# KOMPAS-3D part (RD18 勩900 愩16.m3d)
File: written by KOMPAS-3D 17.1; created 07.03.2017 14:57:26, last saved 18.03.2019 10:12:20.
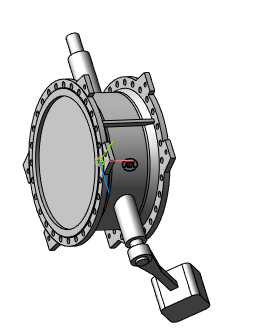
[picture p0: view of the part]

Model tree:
1. Операция без истории:2  (labels: Сталь 20  ГОСТ 1050-88)

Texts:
  RD18 Ду100 Ру16
  RD18 Ду150 Ру16
  RD18 Ду200 Ру16
  RD18 Ду250 Ру16
  RD18 Ду300 Ру16
  RD18 Ду350 Ру16
  RD18 Ду400 Ру10
  RD18 Ду400 Ру16
  RD18 Ду450 Ру10
  RD18 Ду450 Ру16
  RD18 Ду500 Ру10
  RD18 Ду500 Ру16
  RD18 Ду600 Ру10
  RD18 Ду600 Ру16
  RD18 Ду700 Ру10
  RD18 Ду700 Ру16
  RD18 Ду800 Ру10
  RD18 Ду800 Ру16
  RD18 Ду900 Ру10
  RD18 Ду900 Ру16
  RD18 Ду1000 Ру10
  RD18 Ду1000 Ру16
  RD18 Ду1200 Ру16
  RD18 Ду1400 Ру16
